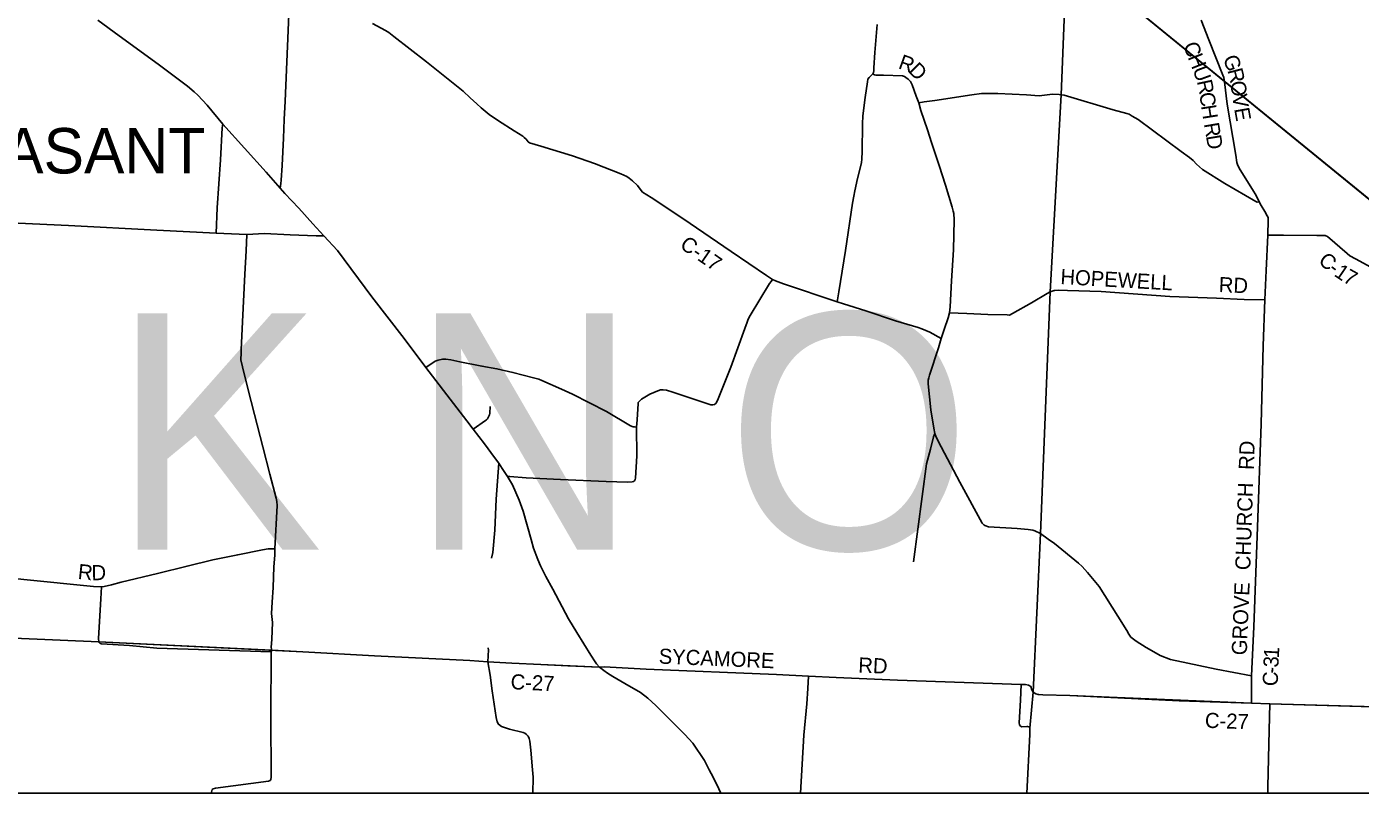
# Model space of a CAD drawing. Extents: x 41.3 to 81.6, y -19.3 to 2.7.
# Drawn here: x 44.697 to 48.932, y -3.595 to -1.162 of the extents above; entities that cross this region are included whole.
import ezdxf

# ---------------------------------------------------------------- set-up
doc = ezdxf.new("R2010")
doc.units = 0
for name, color, linetype in [('Default', 7, 'Continuous'), ('GM_X_County_Road', 7, 'Continuous'), ('GM_X_County_Road_Text', 7, 'Continuous'), ('GM_X_State_Route', 7, 'Continuous'), ('GM_X_Township', 7, 'Continuous'), ('GM_X_Township_Road', 7, 'Continuous'), ('GM_X_Township_Text', 7, 'Continuous'), ('SH_Data', 7, 'Continuous')]:
    doc.layers.add(name, color=color, linetype=linetype)

msp = doc.modelspace()

# ---------------------------------------------------------------- linework, layer by layer
at = {"layer": 'Default'}
msp.add_line((47.6399, -0.6336), (50.5165, -2.9781), dxfattribs=at)
msp.add_lwpolyline([(47.6983, -0.6559), (50.5165, -1.6863), (50.5165, -2.9781), (47.6883, -0.6731)], dxfattribs=at)
at = {"layer": 'GM_X_County_Road'}
for points in [[(48.6384, -1.8242), (48.6399, -1.7764), (48.639, -1.7674), (48.6365, -1.7626), (48.6285, -1.7487), (48.6171, -1.7301), (48.6108, -1.7185), (48.6009, -1.6985), (48.5895, -1.6792), (48.5504, -1.6171), (48.5434, -1.6032), (48.5399, -1.5932), (48.5365, -1.5698), (48.5095, -1.4079), (48.5006, -1.3376), (48.4984, -1.3235), (48.4959, -1.3164), (48.4513, -1.2042), (48.4266, -1.1421)], [(45.7949, -1.1524), (45.8366, -1.1747), (45.8474, -1.1809), (45.8626, -1.193), (45.9673, -1.2735), (46.0831, -1.367), (46.1059, -1.3885), (46.1265, -1.4073), (46.1407, -1.4194), (46.1658, -1.4412), (46.196, -1.4611), (46.2455, -1.4932), (46.2732, -1.5102), (46.2773, -1.5138), (46.283, -1.5196), (46.2893, -1.5274), (46.2941, -1.5313), (46.3295, -1.541), (46.43, -1.5721), (46.5008, -1.597), (46.5837, -1.6291), (46.6028, -1.6377), (46.6107, -1.6426), (46.6205, -1.6514), (46.6364, -1.6664), (46.6452, -1.6783), (46.6528, -1.6871), (46.6804, -1.7048), (46.7808, -1.7711), (46.9342, -1.8763), (47.0464, -1.9518), (47.0658, -1.9648), (47.075, -1.9685), (47.1008, -1.9784), (47.2714, -2.0351), (47.2912, -2.0417), (47.362, -2.0641), (47.4564, -2.096), (47.5285, -2.1171), (47.5397, -2.1211), (47.5652, -2.1323), (47.6015, -2.1517), (47.6111, -2.1233), (47.623, -2.0859), (47.6271, -2.0709)], [(47.3981, -1.1557), (47.3902, -1.2438), (47.3877, -1.2929), (47.3872, -1.3025), (47.3862, -1.3076), (47.3839, -1.3117), (47.389, -1.3147), (47.3938, -1.3163), (47.4178, -1.3166), (47.4786, -1.3187), (47.4845, -1.3206), (47.4891, -1.3233), (47.4961, -1.3288), (47.5037, -1.3366), (47.5087, -1.3469), (47.5214, -1.3824), (47.5301, -1.4043), (47.5369, -1.4285), (47.5576, -1.4893), (47.5709, -1.5299), (47.5947, -1.6027), (47.6145, -1.6655), (47.6358, -1.7351), (47.6395, -1.7473), (47.641, -1.7557), (47.6427, -1.7749), (47.6403, -1.8708), (47.634, -1.9693), (47.6292, -2.051), (47.6271, -2.0709)], [(43.8136, -1.7386), (43.8235, -1.7369), (44.2133, -1.7575), (44.3416, -1.7695), (44.5781, -1.7814), (44.83, -1.7933), (45.1107, -1.8082), (45.2986, -1.8171), (45.3963, -1.8221), (45.4528, -1.819), (45.534, -1.8224), (45.6163, -1.8262), (45.6407, -1.8258)], [(47.9619, -1.9991), (47.9733, -1.9981), (48.0024, -1.9998), (48.1087, -2.003), (48.3272, -2.0189), (48.4749, -2.0236), (48.5636, -2.0276), (48.6293, -2.0295), (48.6333, -1.9358), (48.6384, -1.8242), (48.6877, -1.8241), (48.7935, -1.8247), (48.8204, -1.8252), (48.823, -1.8262), (48.8278, -1.8284), (48.8906, -1.8824), (48.8992, -1.8891), (48.9168, -1.8992), (48.9657, -1.9258)], [(47.6271, -2.0709), (47.6271, -2.0709), (47.6827, -2.0725), (47.7493, -2.0753), (47.8111, -2.0773), (47.8178, -2.0774), (47.8281, -2.0724), (47.888, -2.0391), (47.9378, -2.0089), (47.9474, -2.0041), (47.9595, -1.9993), (47.9619, -1.9991)], [(48.5864, -3.309), (48.5866, -3.2223), (48.5944, -3.0669), (48.606, -2.7508), (48.6176, -2.4226), (48.6237, -2.1749), (48.6293, -2.0295)], [(44.9346, -2.9404), (44.9437, -2.9387), (44.9667, -2.9339), (44.9968, -2.9255), (45.1126, -2.8982), (45.2068, -2.8743), (45.2881, -2.8545), (45.3675, -2.8383), (45.4459, -2.823), (45.4645, -2.8198), (45.4744, -2.8189), (45.4856, -2.8199), (45.4856, -2.8391), (45.4824, -2.8763), (45.4798, -2.9424), (45.4765, -2.9892), (45.4746, -3.0248), (45.4781, -3.0531), (45.4757, -3.1059), (45.4738, -3.133), (45.4754, -3.1413)], [(44.0989, -2.9099), (44.1383, -2.906), (44.1821, -2.9035), (44.1987, -2.9029), (44.2166, -2.9032), (44.2358, -2.9046), (44.2781, -2.908), (44.413, -2.9146), (44.4642, -2.9177), (44.5085, -2.9197), (44.5482, -2.9202), (44.5794, -2.9185), (44.6089, -2.9148), (44.6228, -2.9136), (44.6359, -2.912), (44.6589, -2.9132), (44.688, -2.9169), (44.9096, -2.9388), (44.9346, -2.9404)], [(45.4754, -3.1413), (45.5737, -3.146), (45.8018, -3.1589), (46.1042, -3.174), (46.1617, -3.1779), (46.2378, -3.1823), (46.3299, -3.1865), (46.4154, -3.1903), (46.516, -3.1947), (46.5305, -3.1937), (46.664, -3.201), (47.0786, -3.2182), (47.1798, -3.2237), (47.2673, -3.2282), (47.4621, -3.2359), (47.855, -3.2495), (47.8688, -3.2498), (47.8784, -3.2525), (47.8855, -3.2559), (47.8892, -3.2667), (47.8928, -3.2748), (47.902, -3.2801), (47.9094, -3.2815), (47.9117, -3.2818)], [(47.9117, -3.2818), (47.9235, -3.2831), (48.0099, -3.2846), (48.3567, -3.3015), (48.5864, -3.309), (48.645, -3.3113)], [(48.638, -3.5953), (48.6385, -3.5749), (48.6426, -3.3948), (48.645, -3.3113)], [(48.645, -3.3113), (49.0082, -3.3216), (49.6175, -3.339), (49.8655, -3.349), (50.2043, -3.3575)]]:
    msp.add_lwpolyline(points, dxfattribs=at)
at = {"layer": 'GM_X_State_Route'}
msp.add_lwpolyline([(46.9018, -3.5953), (46.8956, -3.5816), (46.8773, -3.5445), (46.8647, -3.5204), (46.8497, -3.4915), (46.8124, -3.436), (46.7875, -3.4086), (46.7248, -3.3466), (46.6953, -3.3168), (46.6692, -3.2936), (46.646, -3.2754), (46.5962, -3.2473), (46.5583, -3.2245), (46.5414, -3.2138), (46.5303, -3.2058), (46.516, -3.1947), (46.5069, -3.1839), (46.5026, -3.1781), (46.4882, -3.1571), (46.444, -3.0846), (46.4173, -3.0416), (46.3675, -2.9471), (46.3462, -2.9074), (46.3292, -2.8738), (46.3204, -2.8535), (46.3067, -2.8173), (46.2992, -2.7898), (46.2743, -2.6999), (46.2616, -2.6645), (46.2396, -2.6168), (46.2243, -2.5901), (46.2067, -2.5641), (46.1961, -2.5477), (46.1825, -2.5292), (46.1511, -2.4865), (46.1147, -2.4397), (46.0944, -2.4134), (46.0627, -2.3717), (45.965, -2.2439), (45.8954, -2.1517), (45.7932, -2.0198), (45.6839, -1.8731), (45.6407, -1.8258), (45.606, -1.7882), (45.5612, -1.7387), (45.5166, -1.6919), (45.5017, -1.675), (45.4573, -1.6245), (45.3205, -1.4721), (45.2704, -1.4118), (45.2405, -1.3798), (45.2287, -1.3687), (45.2082, -1.3515), (45.1149, -1.2817), (44.9912, -1.1909), (44.9227, -1.1416)], dxfattribs=at)
at = {"layer": 'GM_X_Township'}
for points in [[(49.8429, 0.9122), (48.8731, 0.9493), (48.8673, 0.9496), (48.8494, 0.9506), (48.7166, 0.9552), (48.2508, 0.9768), (48.0986, 0.982), (48.0597, 0.2729), (48.0177, -0.5949), (47.9927, -1.1134), (47.9826, -1.3785), (47.9474, -2.0041), (47.9161, -2.7711), (47.8928, -3.2748), (47.902, -3.2801), (47.9094, -3.2815), (47.9235, -3.2831), (48.0099, -3.2846), (48.5864, -3.309), (48.645, -3.3113), (49.6175, -3.339)], [(47.9927, -1.1134), (47.9826, -1.3785), (47.9474, -2.0041), (47.9161, -2.7711), (47.8928, -3.2748), (47.8892, -3.2667), (47.8855, -3.2559), (47.8784, -3.2525), (47.8688, -3.2498), (47.855, -3.2495), (47.4621, -3.2359), (47.2673, -3.2282), (47.1798, -3.2237), (47.0786, -3.2182), (46.664, -3.201), (46.5305, -3.1937), (46.516, -3.1947), (46.4154, -3.1903), (46.3299, -3.1865), (46.2378, -3.1823), (46.1617, -3.1779), (46.1042, -3.174), (45.8018, -3.1589), (45.5737, -3.146), (45.4754, -3.1413), (44.9265, -3.1148), (44.1153, -3.0795)], [(43.5273, -3.5953), (47.8733, -3.5953), (47.8827, -3.4088), (47.8828, -3.3881), (47.8928, -3.2748), (47.8892, -3.2667), (47.8855, -3.2559), (47.8784, -3.2525), (47.8688, -3.2498), (47.855, -3.2495), (47.4621, -3.2359), (47.2673, -3.2282), (47.1798, -3.2237), (47.0786, -3.2182), (46.664, -3.201), (46.5305, -3.1937), (46.516, -3.1947), (46.3299, -3.1865), (46.2378, -3.1823), (46.1617, -3.1779), (46.1042, -3.174), (45.8018, -3.1589), (45.5737, -3.146), (44.9265, -3.1148), (44.1153, -3.0795)], [(47.8928, -3.2748), (47.8828, -3.3881), (47.8827, -3.4088), (47.8733, -3.5953)]]:
    msp.add_lwpolyline(points, dxfattribs=at)
at = {"layer": 'GM_X_Township_Road'}
for points in [[(45.5017, -1.675), (45.5047, -1.6605), (45.5058, -1.6493), (45.5082, -1.6025), (45.5126, -1.5165), (45.5148, -1.4573), (45.5177, -1.3989), (45.5251, -1.2241), (45.532, -1.0718), (45.5352, -1.0164)], [(47.2714, -2.0351), (47.2763, -2.004), (47.2977, -1.8727), (47.3199, -1.7222), (47.3234, -1.7001), (47.3265, -1.6832), (47.3359, -1.6445), (47.3486, -1.5939), (47.3497, -1.5821), (47.35, -1.5593), (47.3517, -1.4708), (47.3523, -1.4454), (47.3597, -1.3868), (47.3667, -1.3369), (47.3687, -1.3292), (47.3729, -1.3231), (47.3839, -1.3117)], [(47.5301, -1.4043), (47.5475, -1.401), (47.5808, -1.3966), (47.6982, -1.3785), (47.7293, -1.374), (47.7808, -1.3743), (47.8724, -1.3784), (47.9126, -1.3813), (47.9547, -1.3763), (47.976, -1.378)], [(47.976, -1.378), (47.9826, -1.3785), (47.9919, -1.3799), (48.1473, -1.4262), (48.1905, -1.4373), (48.1979, -1.4399), (48.2078, -1.4458), (48.2263, -1.4564), (48.3636, -1.558), (48.3901, -1.577), (48.4012, -1.5874), (48.412, -1.599), (48.421, -1.6074), (48.4309, -1.6151), (48.5015, -1.6604), (48.6002, -1.7171), (48.6047, -1.7188), (48.6108, -1.7185)], [(45.3205, -1.4721), (45.3178, -1.4834), (45.313, -1.5854), (45.3021, -1.7373), (45.2986, -1.8171)], [(45.3963, -1.8221), (45.394, -1.8734), (45.3897, -1.9475), (45.3829, -2.0992), (45.3786, -2.1881), (45.378, -2.2044), (45.3773, -2.2118), (45.3773, -2.2201), (45.3824, -2.2416), (45.4, -2.3106), (45.421, -2.3931), (45.4472, -2.4955), (45.4692, -2.5828), (45.4896, -2.6591), (45.4915, -2.6694), (45.4922, -2.6816), (45.4856, -2.8199)], [(46.6332, -2.4334), (46.6357, -2.4103), (46.6389, -2.3581), (46.6392, -2.3555), (46.6415, -2.3527), (46.6499, -2.3447), (46.676, -2.3284), (46.7011, -2.3178), (46.7101, -2.315), (46.7185, -2.3148), (46.7287, -2.3162), (46.7488, -2.3219), (46.8697, -2.3622), (46.8758, -2.3626), (46.8815, -2.361), (46.8864, -2.3576), (46.8933, -2.3429), (46.9332, -2.2427), (46.9778, -2.12), (46.9851, -2.1002), (46.9887, -2.0909), (46.995, -2.0788), (47.0563, -1.9769), (47.0609, -1.9706), (47.0658, -1.9648)], [(47.6015, -2.1517), (47.5931, -2.1811), (47.5642, -2.268), (47.5622, -2.2764), (47.5599, -2.284), (47.5601, -2.2962), (47.5684, -2.3788), (47.5776, -2.4363), (47.5807, -2.4537), (47.5847, -2.4617), (47.5919, -2.4779), (47.6608, -2.6074), (47.7313, -2.7378), (47.7364, -2.743), (47.7399, -2.7457), (47.7517, -2.7493), (47.8422, -2.755), (47.8775, -2.7576), (47.8921, -2.7598), (47.8981, -2.7626)], [(46.6332, -2.4334), (46.6274, -2.4327), (46.6233, -2.432), (46.6147, -2.4287), (46.5389, -2.3831), (46.4308, -2.3284), (46.3959, -2.3127), (46.3326, -2.2849), (46.3231, -2.2812), (46.3064, -2.2767), (46.241, -2.2593), (46.1903, -2.248), (46.1428, -2.2392), (46.0729, -2.2264), (46.0439, -2.2193), (46.0281, -2.2179), (46.0177, -2.2176), (46.0038, -2.2203), (45.9944, -2.224), (45.965, -2.2439)], [(46.1147, -2.4397), (46.1541, -2.4122), (46.1572, -2.4096), (46.1602, -2.4066), (46.163, -2.4026), (46.1652, -2.3983), (46.1666, -2.3942), (46.1676, -2.3889), (46.1695, -2.3678)], [(46.2243, -2.5901), (46.2313, -2.5894), (46.283, -2.5936), (46.3924, -2.599), (46.5372, -2.6054), (46.6053, -2.6075), (46.6204, -2.6066), (46.6244, -2.6053), (46.6272, -2.6031), (46.6294, -2.5992), (46.6306, -2.5947), (46.6347, -2.5242), (46.6332, -2.4334)], [(47.5807, -2.4537), (47.577, -2.4636), (47.567, -2.5029), (47.5549, -2.5499), (47.5129, -2.8606)], [(46.1734, -2.8491), (46.1777, -2.8313), (46.1843, -2.7604), (46.1878, -2.6618), (46.1961, -2.5477)], [(47.8981, -2.7626), (47.9161, -2.7711), (47.9411, -2.7892), (47.9609, -2.8025), (48.0375, -2.8649), (48.049, -2.8752), (48.0662, -2.8949), (48.1032, -2.9394), (48.1626, -3.0331), (48.1909, -3.0791), (48.1966, -3.0901), (48.2039, -3.0994), (48.2205, -3.112), (48.2521, -3.1321), (48.2834, -3.1509), (48.2965, -3.1583), (48.3298, -3.1704), (48.4748, -3.2014), (48.5866, -3.2223)], [(44.9346, -2.9404), (44.9327, -2.9782), (44.9254, -3.1035), (44.9265, -3.1148), (44.9279, -3.1166)], [(44.9279, -3.1166), (44.9302, -3.1196), (44.9344, -3.1213), (45.0234, -3.1266), (45.1102, -3.1343), (45.4734, -3.1467)], [(46.1617, -3.1779), (46.1635, -3.1396), (46.1625, -3.1343), (46.1626, -3.1335)], [(45.2837, -3.5953), (45.2839, -3.5914), (45.2849, -3.5872), (45.2865, -3.5834), (45.2897, -3.5812), (45.297, -3.5786), (45.4651, -3.5564), (45.4699, -3.5545), (45.4722, -3.5513), (45.4734, -3.5439), (45.4727, -3.3514), (45.4734, -3.1467), (45.4754, -3.1413)], [(46.305, -3.5953), (46.3058, -3.5444), (46.3036, -3.5209), (46.2978, -3.4588), (46.2947, -3.4303), (46.2929, -3.4213), (46.2894, -3.414), (46.2847, -3.4084), (46.279, -3.4046), (46.2737, -3.402), (46.2307, -3.3916), (46.2049, -3.3832), (46.195, -3.376), (46.1917, -3.3688), (46.1884, -3.3547), (46.1754, -3.27), (46.1688, -3.2204), (46.1617, -3.1779)], [(47.1798, -3.2237), (47.1782, -3.2628), (47.1748, -3.3118), (47.1653, -3.4112), (47.1545, -3.5953)], [(47.8828, -3.3901), (47.8828, -3.3881), (47.8805, -3.3848), (47.8765, -3.3833), (47.873, -3.3833), (47.8577, -3.3844), (47.8531, -3.3823), (47.8498, -3.3777), (47.8488, -3.3715), (47.853, -3.2993), (47.855, -3.2495)], [(47.8733, -3.5953), (47.8827, -3.4088), (47.8828, -3.3901)]]:
    msp.add_lwpolyline(points, dxfattribs=at)
at = {"layer": 'SH_Data'}
msp.add_line((43.2645, -3.5953), (50.2645, -3.5953), dxfattribs=at)

# ---------------------------------------------------------------- texts
at = {"layer": 'Default'}
msp.add_text('K N O', height=0.75, dxfattribs=at).set_placement((44.9676, -2.8217))
at = {"layer": 'GM_X_County_Road_Text'}
for s, rotation, p in [('C', 290.2299, (48.3692, -1.2205)), ('R', 340.0529, (47.4622, -1.2939)), ('H', 291.5986, (48.3833, -1.2587)), ('G', 290.646, (48.4951, -1.2623)), ('D', 314.9717, (47.4946, -1.3044)), ('U', 290.2346, (48.3987, -1.2977)), ('R', 284.4007, (48.5096, -1.3005)), ('R', 282.1588, (48.4128, -1.3356)), ('O', 277.5552, (48.5191, -1.3372)), ('C', 277.3695, (48.421, -1.3731)), ('V', 278.5298, (48.5248, -1.3799)), ('H', 278.9707, (48.4262, -1.4136)), ('E', 280.0042, (48.5313, -1.423)), ('R', 279.5124, (48.4353, -1.4704)), ('D', 279.594, (48.4418, -1.5094)), ('C-17', 325.5448, (46.7682, -1.8625)), ('C', 319.4393, (48.7958, -1.91)), ('HOPEWELL', 356.7302, (47.9789, -1.979)), ('-', 322.0013, (48.8276, -1.9372)), ('1', 325.8765, (48.846, -1.9514)), ('7', 330.6209, (48.8741, -1.9703)), ('RD', 357.5314, (48.4819, -2.0044)), ('RD', 88.0243, (48.5938, -2.5696)), ('CHURCH', 88.0747, (48.5826, -2.8878)), ('R', 354.0451, (44.8582, -2.9147)), ('D', 0.5112, (44.9032, -2.9191)), ('GROVE', 87.6223, (48.5713, -3.1579)), ('SYCAMORE', 357.65, (46.7036, -3.1836)), ('RD', 357.5314, (47.3372, -3.2117)), ('3', 86.9856, (48.6717, -3.1968)), ('1', 86.8499, (48.6732, -3.1673)), ('C-27', 357.2631, (46.2331, -3.2646)), ('C', 88.8993, (48.6701, -3.2555)), ('-', 87.5013, (48.6708, -3.2164)), ('C-27', 357.9422, (48.438, -3.3872))]:
    msp.add_text(s, height=0.048, rotation=rotation, dxfattribs=at).set_placement(p)
at = {"layer": 'GM_X_Township_Text'}
msp.add_text('PLEASANT', height=0.144, rotation=0, dxfattribs=at).set_placement((44.2585, -1.628))

doc.saveas('drawing.dxf')
